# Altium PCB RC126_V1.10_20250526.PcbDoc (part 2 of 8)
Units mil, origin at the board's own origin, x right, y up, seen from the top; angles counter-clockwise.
Board outline 6299.62 x 3544.12 mil, 4 copper layers (Top, GND, Power, Bottom), stack 35.4 mil thick; 509 components, 417 nets, 1867 pads, 2150 vias.
Unrouted connection lines stored in the file: 1451.
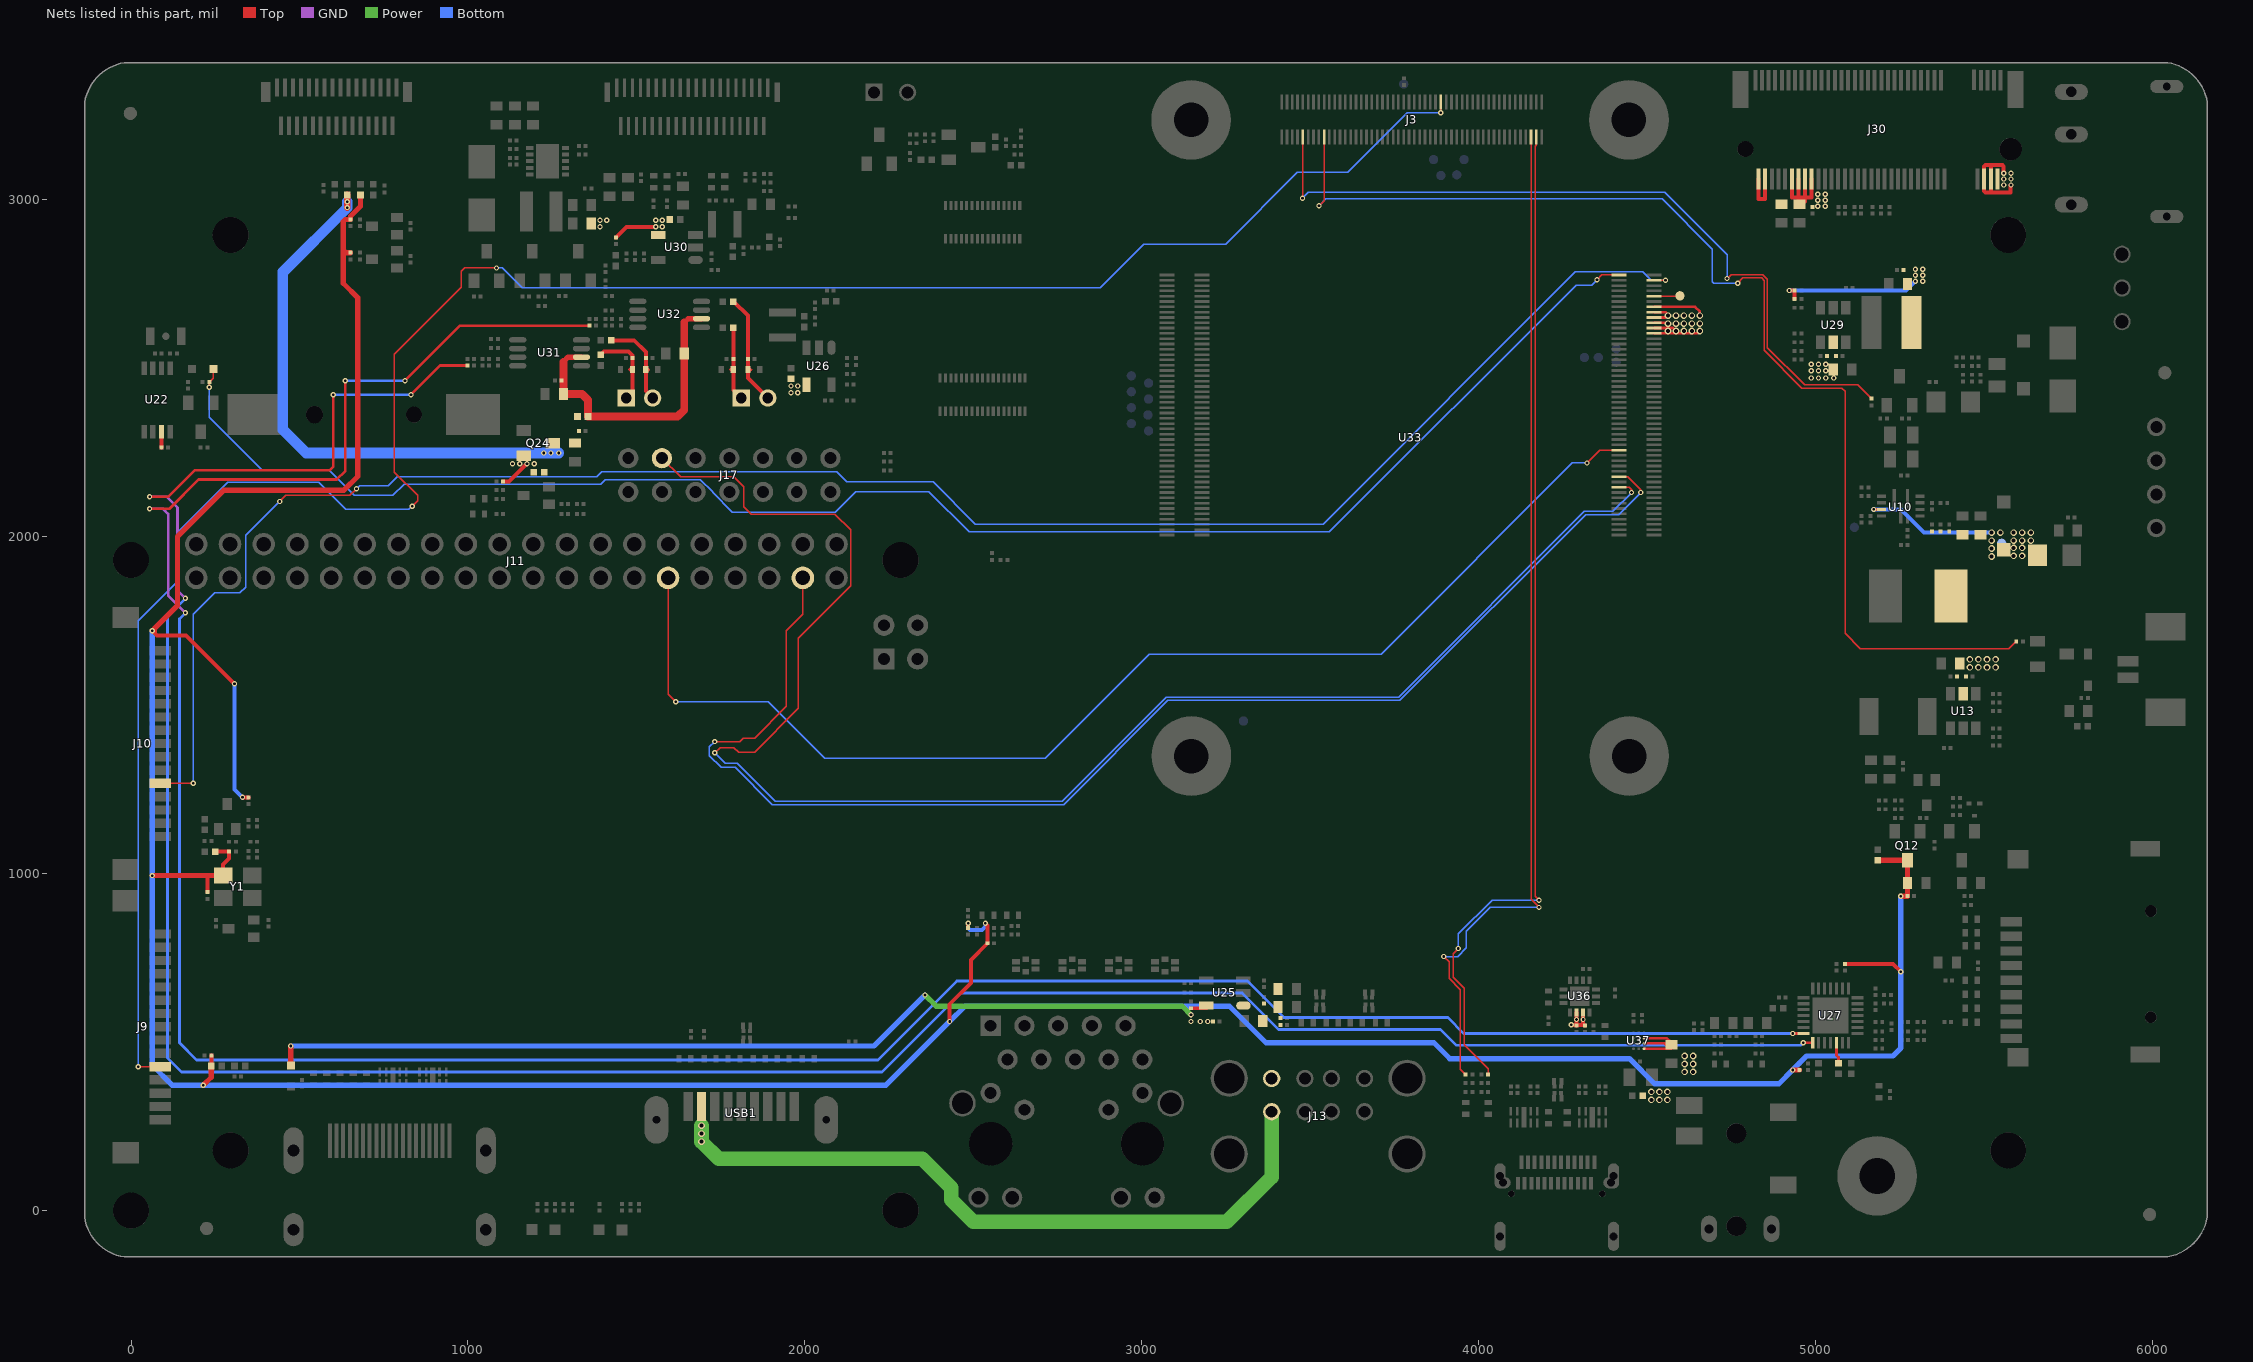
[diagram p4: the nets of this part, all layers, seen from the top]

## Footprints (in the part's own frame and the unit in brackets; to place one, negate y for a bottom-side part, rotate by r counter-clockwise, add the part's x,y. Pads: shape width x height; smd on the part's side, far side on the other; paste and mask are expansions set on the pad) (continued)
ESD_D0402 [mm]
  rect 0.4x0.55 smd: 1(-0.45,0) 2(0.45,0)
  Top region: 0.318,0.178 0.152,0.013 0.324,-0.159 0.324,0.165 0.318,0.165 0.318,0.178
  Top region: 0.368,0.279 0.095,0.006 0.375,-0.273 0.375,0.267 0.368,0.267 0.368,0.279
  Top region: -0.305,-0.165 -0.14,0 -0.311,0.171 -0.311,-0.152 -0.305,-0.152 -0.305,-0.165
  Top region: -0.356,-0.267 -0.083,0.006 -0.362,0.286 -0.362,-0.254 -0.356,-0.254 -0.356,-0.267
  Top lines w0.051: -0.495,-0.178 -0.305,-0.178 ; -0.495,0.191 -0.305,0.191 ; -0.457,-0.14 -0.267,-0.14 ; -0.457,0.152 -0.267,0.152 ; -0.432,0.114 -0.241,0.114 ; -0.419,-0.102 -0.229,-0.102 ; -0.406,0.089 -0.216,0.089 ; -0.394,-0.064 -0.203,-0.064 ; -0.381,0.064 -0.191,0.064 ; -0.356,-0.038 -0.165,-0.038 ; -0.343,0.038 -0.152,0.038 ; -0.33,-0.013 -0.14,-0.013 ; -0.318,0.013 -0.127,0.013 ; 0.14,0 0.33,0 ; 0.152,0.025 0.343,0.025 ; 0.165,-0.025 0.356,-0.025 ; 0.178,0.051 0.368,0.051 ; 0.203,-0.051 0.394,-0.051 ; 0.216,0.076 0.406,0.076 ; 0.229,-0.076 0.419,-0.076 ; 0.241,0.114 0.432,0.114 ; 0.254,-0.102 0.445,-0.102 ; 0.279,-0.14 0.47,-0.14 ; 0.279,0.152 0.47,0.152 ; 0.318,-0.178 0.508,-0.178 ; 0.318,0.191 0.508,0.191
  silkscreen extent -0.82,-0.41 0.85,0.42
FB0201 [mm]
  rect 0.3x0.3 smd: 1(-0.25,0) 2(0.25,0)
  silkscreen extent -0.5,-0.25 0.5,0.25
FB0402 [mm]
  rect 0.5x0.5 smd: 1(-0.4,0) 2(0.4,0)
  silkscreen extent -0.8,-0.4 0.8,0.4
FB0603 [mm]
  rect 0.7x0.9 smd: 1(-0.7,0) 2(0.7,0)
  silkscreen extent -1.2,-0.6 1.2,0.6
FB1206 [mm]
  rect 1.4x1.6 smd mask+0.05: 1(-1.3,0) 2(1.3,0)
  silkscreen extent -2.2,-1 2.2,1
FPC_15_1D0_LIE [mil]
  rect 27.6x63 smd: 1(-551.17,0) 2(-511.77,0) 3(-472.47,0) 4(-433.07,0) 5(-393.7,0) 6(-354.33,0) 7(-314.96,0) 8(-275.59,0) 9(-236.22,0) 10(-196.85,0) 11(-157.48,0) 12(-118.11,0) 13(-78.74,0) 14(-39.37,0) 15(0,0)
  rect 63x78.7 smd: 16(98.43,102.4) 17(-649.57,102.4)
  silkscreen extent -661,-77 114,193
FPC_31P_0D3_LIE [mm]
  rect 0.3x1.372 smd: 1(0,0) 2(0.3,2.875) 3(0.6,0) 4(0.9,2.875) 5(1.2,0) 6(1.5,2.875) 7(1.8,0) 8(2.1,2.875) 9(2.4,0) 10(2.7,2.875) 11(3,0) 12(3.3,2.875) 13(3.6,0) 14(3.9,2.875) 15(4.2,0) 16(4.5,2.875) 17(4.8,0) 18(5.1,2.875) 19(5.4,0) 20(5.7,2.875) 21(6,0) 22(6.3,2.875) 23(6.6,0) 24(6.9,2.875) 25(7.2,0) 26(7.5,2.875) 27(7.8,0) 28(8.1,2.875) 29(8.4,0) 30(8.7,2.875) 31(9,0)
  rect 0.7x1.5 smd: 32(9.84,0.335) 33(-0.84,0.335)
  silkscreen extent -1.07,-1.53 10,3.31
FPC_39P_0D3_LIE [mil]
  rect 54x10 smd: 1(0,0) 2(-113.18,11.81) 3(0,23.62) 4(-113.18,35.43) 5(0,47.24) 6(-113.18,59.06) 7(0,70.87) 8(-113.18,82.68) 9(0,94.49) 10(-113.18,106.3) 11(0,118.11) 12(-113.18,129.92) 13(0,141.73) 14(-113.18,153.54) 15(0,165.35) 16(-113.18,177.17) 17(0,188.98) 18(-113.18,200.79) 19(0,212.6) 20(-113.18,224.41) 21(0,236.22) 22(-113.18,248.03) 23(0,259.84) 24(-113.18,271.65) 25(0,283.46) 26(-113.18,295.28) 27(0,307.09) 28(-113.18,318.9) 29(0,330.71) 30(-113.18,342.52) 31(0,354.33) 32(-113.18,366.14) 33(0,377.95) 34(-113.18,389.76) 35(0,401.57) 36(-113.18,413.39) 37(0,425.2) 38(-113.18,437.01) 39(0,448.82)
  rect 59.06x15.75 smd: 40(-13.18,476.38) 41(-13.18,-27.56)
  silkscreen extent -130,-33 71,483
HOLE_2D7_6D0_A [mm]
  round 6 / inner round 3.2 / far side round 6 hole 2.7: 1(0,0)
HOLE_R6_2D7MM [mm]
  round 2.7 hole 2.7 unplated: 1(0,0)
  Top keep-out region: 3.003,0 2.774,1.149 2.123,2.123 1.149,2.774 0,3.003 0,3.003 -1.149,2.774 -2.123,2.123 -2.774,1.149 -3.003,0 -3.003,0 -2.774,-1.149 -2.123,-2.123 -1.149,-2.774 0,-3.003 0,-3.003 1.149,-2.774 2.123,-2.123 2.774,-1.149 3.003,0
  Bottom keep-out region: 3.003,0 2.774,1.149 2.123,2.123 1.149,2.774 0,3.003 0,3.003 -1.149,2.774 -2.123,2.123 -2.774,1.149 -3.003,0 -3.003,0 -2.774,-1.149 -2.123,-2.123 -1.149,-2.774 0,-3.003 0,-3.003 1.149,-2.774 2.123,-2.123 2.774,-1.149 3.003,0
L_2520 [mm]
  rect 0.6x2 smd: 1(0.947,0.006) 2(-0.953,0.006)
  Top keep-out region: -0.66,1 0.63,1 0.63,-1 -0.66,-1 -0.66,1
  silkscreen extent -1.33,-1.07 1.33,1.08
L_3015 [mil]
  rect 39x118 smd mask+3: 1(-44.85,0) 2(43.43,0)
  silkscreen extent -20,-59 20,59
L_4020 [mm]
  rect 1.5x4 smd mask+0.05: 1(-1.5,0) 2(1.5,0)
  silkscreen extent -2.1,-2.1 2.1,2.1
L_5020 [mm]
  rect 1.4x2.8 smd: 1(-2.2,0) 2(2.2,0)
  silkscreen extent -2.7,-2.55 2.7,2.55
L_6050 [mm]
  rect 2.5x4 smd: 1(-2.56,-0.07) 2(2.39,-0.07)
  silkscreen extent -3.79,-3.35 3.6,3.28
LED_D0603 [mm]
  rect 0.8x0.8 smd: 1(-0.869,0.001) 2(0.869,-0.001)
  silkscreen extent -1.41,-0.65 1.41,0.65
M2-M_KEY_SM_75_0D5 [mm]
  rect 0.3x1.55 smd mask+0.05: 1(-9.25,3.725) 2(-9,-3.725) 3(-8.75,3.725) 4(-8.5,-3.725) 5(-8.25,3.725) 6(-8,-3.725) 7(-7.75,3.725) 8(-7.5,-3.725) 9(-7.25,3.725) 10(-7,-3.725) 11(-6.75,3.725) 12(-6.5,-3.725) 13(-6.25,3.725) 14(-6,-3.725) 15(-5.75,3.725) 16(-5.5,-3.725) 17(-5.25,3.725) 18(-5,-3.725) 19(-4.75,3.725) 20(-4.5,-3.725) 21(-4.25,3.725) 22(-4,-3.725) 23(-3.75,3.725) 24(-3.5,-3.725) 25(-3.25,3.725) 26(-3,-3.725) 27(-2.75,3.725) 28(-2.5,-3.725) 29(-2.25,3.725) 30(-2,-3.725) 31(-1.75,3.725) 32(-1.5,-3.725) 33(-1.25,3.725) 34(-1,-3.725) 35(-0.75,3.725) 36(-0.5,-3.725) 37(-0.25,3.725) 38(0,-3.725) 39(0.25,3.725) 40(0.5,-3.725) 41(0.75,3.725) 42(1,-3.725) 43(1.25,3.725) 44(1.5,-3.725) 45(1.75,3.725) 46(2,-3.725) 47(2.25,3.725) 48(2.5,-3.725) 49(2.75,3.725) 50(3,-3.725) 51(3.25,3.725) 52(3.5,-3.725) 53(3.75,3.725) 54(4,-3.725) 55(4.25,3.725) 56(4.5,-3.725) 57(4.75,3.725) 58(5,-3.725) 67(7.25,3.75) 68(7.5,-3.725) 69(7.75,3.725) 70(8,-3.725) 71(8.25,3.725) 72(8.5,-3.725) 73(8.75,3.725) 74(9,-3.725) 75(9.25,3.725)
  round 1.2 hole 1.2 unplated: 76(-10,-1.475)
  round 1.7 hole 1.7 unplated: 77(10,-1.475)
  rect 1.2x2.8 smd mask+0.05: G1(-10.35,3.025) G2(10.35,3.025)
  silkscreen extent -9.54,-2.7 8.8,4.95
MARK [mm]
  round 1 smd: 1(0,0)
  silkscreen extent -1.65,-1.65 1.65,1.65
MLP14_0D5_2D5 [mm]
  rect 0.6x0.3 smd: 1(-1.21,0.5) 2(-1.21,0) 3(-1.21,-0.5) 8(1.21,-0.5) 9(1.21,0) 10(1.21,0.5)
  rect 0.3x0.6 smd: 4(-0.75,-1.21) 5(-0.25,-1.21) 6(0.25,-1.21) 7(0.75,-1.21) 11(0.75,1.21) 12(0.25,1.21) 13(-0.25,1.21) 14(-0.75,1.21)
  rect 1.45x1.45 smd: 15(0,0)
  silkscreen extent -2.48,-1.25 1.25,1.25
MSOP8_0D65_3 [mil]
  rect 40x16 smd mask+2.5: 1(0,0) 2(0,-25.59) 3(0,-51.18) 4(0,-76.77) 5(188.98,-76.77) 6(188.98,-51.18) 7(188.98,-25.59) 8(188.98,0)
  silkscreen extent -20,-90 209,40
MSOP8_0D65_5D0 [mm]
  oval 1.3x0.41 smd mask+0.05: 1(-2.4,0.975) 2(-2.4,0.325) 3(-2.4,-0.325) 4(-2.4,-0.975) 5(2.4,-0.975) 6(2.4,-0.325) 7(2.4,0.325) 8(2.4,0.975)
  silkscreen extent -2.71,-1.63 1.6,1.92
OSC_SM2_3D2X1D5 [mm]
  rect 0.65x1.3 smd: 1(0,0) 2(2.35,0)
  round 0.55 smd: 3(1.175,0)
  silkscreen extent -0.6,-0.8 2.9,0.8
OSC_SM4_3D2X2D5 [mm]
  rect 1.4x1.2 smd: 1(-1.1,-0.85) 2(1.1,-0.85) 3(1.1,0.85) 4(-1.1,0.85)
  silkscreen extent -1.6,-2.02 1.6,1.26
QFN12_0D5_2 [mm]
  rect 1.5x0.25 smd: 1(-0.55,0.5) 2(-0.55,-0.5) 7(0.55,0)
  rect 0.25x0.7 smd: 3(-0.75,-1.45) 4(-0.25,-1.45) 5(0.25,-1.45) 6(0.75,-1.45) 9(0.75,1.45) 10(0.25,1.45) 11(-0.25,1.45) 12(-0.75,1.45)
  rect 0.7x0.25 smd: 8(0.95,0.5)
  silkscreen extent -1.81,-1.5 1,1.5
QFN28_0D45_4 [mm]
  rect 0.9x0.25 smd mask+0.05: 1(-2.05,1.35) 2(-2.05,0.9) 3(-2.05,0.45) 4(-2.05,0) 5(-2.05,-0.45) 6(-2.05,-0.9) 7(-2.05,-1.35) 15(2.05,-1.35) 16(2.05,-0.9) 17(2.05,-0.45) 18(2.05,0) 19(2.05,0.45) 20(2.05,0.9) 21(2.05,1.35)
  rect 0.25x0.9 smd mask+0.05: 8(-1.35,-2.05) 9(-0.9,-2.05) 10(-0.45,-2.05) 11(0,-2.05) 12(0.45,-2.05) 13(0.9,-2.05) 14(1.35,-2.05) 22(1.35,2.05) 23(0.9,2.05) 24(0.45,2.05) 25(0,2.05) 26(-0.45,2.05) 27(-0.9,2.05) 28(-1.35,2.05)
  rect 2.7x2.7 smd mask+0.05: 29(0,0)
  Top keep-out region: -1.524,1.524 -1.524,-1.524 1.524,-1.524 1.524,1.524 -1.524,1.524
  silkscreen extent -2.97,-2 2,2.03
R0201 [mm]
  rect 0.3x0.3 smd: 1(-0.25,0) 2(0.25,0)
  silkscreen extent -0.5,-0.25 0.5,0.25
R0402 [mm]
  rect 0.5x0.5 smd: 1(-0.4,0) 2(0.4,0)
  silkscreen extent -0.8,-0.4 0.8,0.4
R0603 [mm]
  rect 0.7x0.9 smd: 1(-0.7,0) 2(0.7,0)
  silkscreen extent -1.2,-0.6 1.2,0.6
RJ45_LED_TH22_LIE [mm]
  rect 1.524x1.524 hole 0.9 mask+0.05: 1(0,0)
  round 1.524 / inner round 1.1 / far side round 1.524 hole 0.9 mask+0.05: 2(1.27,-2.54) 3(2.54,0) 4(3.81,-2.54) 5(5.08,0) 6(6.35,-2.54) 7(7.62,0) 8(8.89,-2.54) 9(10.16,0) 10(11.43,-2.54) 11(0,-5.06) 12(2.54,-6.33) 13(8.89,-6.33) 14(11.43,-5.06) 18(12.36,-12.95)
  round 1.524 hole 1.02 mask+0.05: 15(-0.92,-12.95) 16(1.62,-12.95) 17(9.82,-12.95)
  round 2 / inner round 2.2 / far side round 2.2 hole 1.6 mask+0.15: 19(-2.13,-5.84) 20(13.57,-5.84)
  round 3.25 hole 3.25: 21(0.005,-8.89) 22(11.435,-8.89)
  silkscreen extent -2.34,-19.63 13.77,1.72
SD_SM9_1D1_15D75 [mm]
  rect 1.6x0.7 smd: 1(-10.516,3.2) 2(-10.516,2.1) 3(-10.516,1) 4(-10.516,-0.1) 5(-10.516,-1.2) 6(-10.516,-2.3) 7(-10.516,-3.4) 8(-10.516,-4.5) 9(-10.516,-5.6)
  rect 1.6x1.4 smd: 10(-10.016,-7) 13(-10.016,7.9)
  rect 2.2x1.2 smd: 11(-0.416,-6.8) 12(-0.416,8.7)
  round 0.9 hole 0.9 unplated: 14(0,4) 15(0,-4)
  silkscreen extent -10.52,-6.4 3.98,8.3
SOD_123 [mm]
  rect 1x1 smd: 1(-1.8,0) 2(1.8,0)
  silkscreen extent -1.11,-0.9 1.13,0.9
SOD_323 [mm]
  rect 0.8x0.6 smd mask+0.05: 1(-1.2,0) 2(1.2,0)
  silkscreen extent -0.67,-0.65 0.64,0.65
SOD_523 [mm]
  rect 0.6x0.6 smd mask+0.05: 1(0,0.8) 2(0,-0.8)
  silkscreen extent -0.4,-0.6 0.4,0.6
SON10_0D5_1 [mm]
  rect 0.2x0.675 smd: 1(-1,-0.437) 2(-0.5,-0.437) 4(0.5,-0.437) 5(1,-0.437) 6(1,0.437) 7(0.5,0.437) 9(-0.5,0.437) 10(-1,0.437)
  rect 0.4x0.775 smd: 3(0,-0.388) 8(0,0.388)
  silkscreen extent -1.46,-1.39 1.25,0.5
SOT23_5 [mm]
  oval 0.6x1.1 smd: 1(-0.95,-1.4)
  rect 0.6x1.1 smd: 2(0,-1.4) 3(0.95,-1.4) 4(0.95,1.4) 5(-0.95,1.4)
  silkscreen extent -2,-1.45 1.5,0.55
SOT23_6 [mm]
  rect 0.7x1 smd mask+0.05: 1(-0.95,-1.3) 2(0,-1.3) 3(0.95,-1.3) 4(0.95,1.3) 5(0,1.3) 6(-0.95,1.3)
  silkscreen extent -1.75,-2.42 1.75,0.7
SOT_23 [mm]
  rect 0.8x1.1 smd: 1(-0.95,-1.1) 2(0.95,-1.1) 3(0,1.1)
  silkscreen extent -1.6,-0.9 1.6,0.9
SOT_323 [mm]
  rect 0.7x0.9 smd: 1(-0.65,-0.95) 2(0.65,-0.95) 3(0,0.95)
  silkscreen extent -1.1,-0.67 1.1,0.67
SOT_723 [mm]
  rect 0.4x0.3 smd: 1(0,0) 2(0.805,0) 3(0.403,0.94)
  silkscreen extent -0.22,-0.17 1.02,1.12
TP_0R70 [mm]
  round 0.7 smd: 1(0,0)
  silkscreen extent -0.45,-0.45 0.45,0.45
TYPEC_SM24P_0D5 [mm]
  rect 0.3x1 smd: A1(1.61,5.59) A2(2.11,5.59) A3(2.61,5.59) A4(3.11,5.59) A5(3.61,5.59) A6(4.11,5.59) A7(4.61,5.59) A8(5.11,5.59) A9(5.61,5.59) A10(6.11,5.59) A11(6.61,5.59) A12(7.11,5.59)
  rect 0.3x0.95 smd: B1(6.86,3.99) B2(6.36,3.99) B3(5.86,3.99) B4(5.36,3.99) B5(4.86,3.99) B6(4.36,3.99) B7(3.86,3.99) B8(3.36,3.99) B9(2.86,3.99) B10(2.36,3.99) B11(1.86,3.99) B12(1.36,3.99)
  oval 0.85x1.9 / inner oval 0.85x1.8 / far side oval 1x2.1 hole 0.6 slot 1.5 at 90 deg: E1(0,4.55) E6(8.56,4.55)
  oval 1.2x0.85 / inner oval 1.2x0.85 / far side oval 1.2x0.9 hole 0.6 slot 1 at 0 deg: E2(0.21,4.04) E5(8.38,4.04)
  oval 0.85x2.2 / inner oval 0.85x2.2 / far side oval 1x2.2 hole 0.6 slot 1.9 at 90 deg: E3(0,0)
  oval 0.85x2.2 / inner oval 0.85x2.2 / far side oval 1x2.25 hole 0.6 slot 1.9 at 90 deg: E4(8.56,0)
  round 0.5 hole 0.5: H1(0.85,3.2) H2(7.71,3.2)
  silkscreen extent -0.24,-2.35 8.87,5.55
USB_SM9_2D0_LIE [mm]
  rect 0.7x2.2 smd: 1(-3,0) 2(-1,0) 3(1,0) 4(3,0) 5(4,0) 6(2,0) 7(0,0) 8(-2,0) 9(-4,0)
  oval 1.8x3.6 / inner oval 0.7x2.6 / far side oval 1.8x3.6 hole 0.584 slot 2.489 at 90 deg: 10(-6.4,-1) 11(6.4,-1)
  silkscreen extent -9.28,-14.64 9.29,0.92
WLCSP12_0D4_1D5 [mm]
  round 0.215 smd mask+0.05: A1(0,0) A2(0.4,0) A3(0.8,0) B1(0,-0.4) B2(0.4,-0.4) B3(0.8,-0.4) C1(0,-0.8) C2(0.4,-0.8) C3(0.8,-0.8) D1(0,-1.2) D2(0.4,-1.2) D3(0.8,-1.2)
  silkscreen extent -0.66,-1.53 1.12,0.61

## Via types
v1: diameter 15.75, hole 7.87, Top to Bottom, 2047 vias
v2: diameter 19.68, hole 11.81, Top to Bottom, 103 vias

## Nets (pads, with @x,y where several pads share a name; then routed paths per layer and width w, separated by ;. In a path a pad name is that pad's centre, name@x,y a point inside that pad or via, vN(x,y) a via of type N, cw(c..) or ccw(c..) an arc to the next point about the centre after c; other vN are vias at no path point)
3V3_PCIE: C217.1 C218.1 C219.1 C223.1 C224.1 C225.1 J30.2 J30.4 J30.12 J30.14 J30.16 J30.18 J30.70 J30.72 J30.74 L21.2 R285.1 | length 1224.6
  Top w11.81: J30.2@4829.92,3061.22 4829.92,3001.97 4849.61,3001.97 J30.4@4849.61,3061.22 ; v1(4921.26,2730.32) R285.1@4937.01,2730.32 C217.1@4937.01,2704.72 ; J30.12@4928.35,3061.22 4928.35,3005.91 4987.4,3005.91 J30.18@4987.4,3061.22 ; J30.14@4948.03,3061.22 4948.03,2994.09 4967.72,2994.09 J30.16@4967.72,3061.22 ; v1(5557.09,3078.74) 5557.09,3098.43 5553.15,3102.36 5518.9,3102.36 ; v1(5578.74,3043.31) 5576.77,3041.34 5576.77,3021.65 5518.9,3021.65 ; 5518.9,3021.65 5503.15,3021.65 5499.21,3025.59 J30.70@5499.21,3061.22 5499.21,3098.43 5503.15,3102.36 5518.9,3102.36 ; 5518.9,3021.65 J30.72@5518.9,3061.22 5518.9,3102.36
  Bottom w11.81: v1(4921.26,2730.32) 5267.72,2730.32 v1(5295.28,2757.87)
  other v1: 5316.93,2757.87 5295.28,2775.59 5316.93,2775.59 5295.28,2793.31 5316.93,2793.31 5005.91,2980.32 5027.56,2980.32 5005.91,2998.03 5027.56,2998.03 5005.91,3015.75 5027.56,3015.75 5557.09,3043.31 5557.09,3061.02 5578.74,3061.02 5578.74,3078.74
3V3_S0: C157.1 C158.1 C194.1 FB1.2 FB3.2 FB4.2 FB14.1 FB15.1 Q12.3 R8.2 R11.2 R164.1 R211.2 R238.1 R248.2 R264.2 R270.2 Y1.4 | length 11029.8
  Top w3.94: 226.38,994.09 228.35,994.09
  Top w11.81: v1(62.99,1720.47) 70.87,1712.6 ; 70.87,1728.35 70.87,1712.6 ; R264.2@226.38,944.88 226.38,994.09 ; FB1.2@238.19,429.13 R211.2@238.19,460.63 ; FB3.2@250,1064.96 C194.1@291.34,1064.96 291.34,1045.27 273.62,1027.56 Y1.4@273.62,994.09 ; v1(307.09,1562.99) 163.39,1706.69 76.77,1706.69 70.87,1712.6 ; v1(330.71,1226.38) R270.2@348.43,1226.38 ; v1(2429.13,561.02) 2429.13,612.2 2492.13,675.2 2492.13,744.09 R238.1@2541.34,793.31 2541.34,846.46 v1(2535.43,852.36) ; R248.2@2484.25,838.58 v1(2484.25,852.36) ; FB14.1@5086.61,732.28 5228.35,732.28 v1(5251.97,708.66)
  Top w15.75: v1(62.99,994.09) 226.38,994.09 ; v1(62.99,1720.47) 70.87,1728.35 137.8,1795.28 137.8,2000 275.59,2137.8 631.89,2137.8 673.23,2179.13 673.23,2708.66 629.92,2751.97 629.92,2850.39 ; v1(214.57,372.05) 238.19,395.67 FB1.2@238.19,429.13 ; 228.35,994.09 Y1.4@273.62,994.09 ; R8.2@651.57,2842.52 637.8,2842.52 629.92,2850.39 ; FB4.2@681.1,3013.78 681.1,2980.32 651.57,2950.79 R11.2@651.57,2940.94 635.83,2940.94 629.92,2935.04 629.92,2850.39 ; v1(4931.1,417.32) FB15.1@4950.79,417.32 ; R164.1@5183.07,1039.37 Q12.3@5271.65,1039.37 C157.1@5271.65,972.44 C158.1@5271.65,933.07 v1(5251.97,933.07)
  Bottom w11.81: v1(307.09,1562.99) 307.09,1250 v1(330.71,1226.38) ; v1(2484.25,852.36) 2484.25,838.58 2490.16,832.68 2525.59,832.68 2535.43,842.52 v1(2535.43,852.36)
  Bottom w15.75: v1(62.99,1720.47) v1(62.99,994.09) 62.99,431.1 122.05,372.05 v1(214.57,372.05) 2240.16,372.05 v1(2429.13,561.02) 2474.41,606.3 3259.84,606.3 3368.11,498.03 3866.14,498.03 3913.39,450.79 4446.85,450.79 4521.65,375.98 4889.76,375.98 v1(4931.1,417.32) 4972.44,458.66 5228.35,458.66 5251.97,482.28 v1(5251.97,708.66) v1(5251.97,933.07)
5V_S0: C297.1 C298.1 FB5.2 FB22.1 Q24.3 R342.1 | length 1641.1
  Top w19.68: v1(641.73,2976.38) FB5.2@641.73,3013.78
  Bottom w31.5: v1(641.73,2994.09) v1(641.73,2976.38) 450.79,2785.43 450.79,2316.93 519.69,2248.03 v1(1269.68,2248.03)
  other v1: 1224.41,2248.03 1246.06,2248.03
5V_SPK_AMP: C282.1 C285.1 C292.1 FB22.2 U31.6 U32.6 | length 898.1
  Top w3.94: C282.1@1277.56,2462.6 1283.46,2462.6
  Top w15.75: 1283.46,2518.7 1297.24,2532.48 U31.6@1336.61,2532.48 ; 1641.73,2634.84 1653.54,2646.65 U32.6@1692.91,2646.65
  Top w23.62: 1283.46,2518.7 1283.46,2462.6 C285.1@1283.46,2423.23 1338.58,2423.23 1356.3,2405.51 FB22.2@1356.3,2356.3 1622.05,2356.3 1641.73,2375.98 C292.1@1641.73,2543.31 1641.73,2634.84
5V_USB_HOST: C198.1 C199.1 C213.1 C214.1 C215.1 C216.1 J13.1 J13.5 U25.1 USB1.1 | length 2164.3
  Top w3.94: USB1.1@1692.91,271.65 USB1.1@1692.91,328.35
  Power w43.31: v2(1692.91,251.97) v2(1692.91,228.35) v2(1692.91,204.72) 1744.09,153.54 2348.43,153.54 2434.06,67.91 2434.06,32.48 2500,-33.46 3251.97,-33.46 3385.04,99.61 J13.1@3385.04,293.31
32KOUT_RTC: R263.2 U22.7 | length 47.2
  Top w11.81: R263.2@90.55,2263.78 U22.7@90.55,2311.02
+5V_INPUT: C90.1 C106.1 C107.1 C144.1 C146.1 C153.1 C154.1 C196.1 C202.1 C211.1 C212.1 C241.1 C255.1 C270.1 C271.1 D1.2 D8.1 FB2.1 L2.2 Q24.2 R18.1 R185.1 R255.1 R277.1 R278.2 R342.2 R344.2 R352.1 TP7.1 U10.5 U13.5 U25.5 U26.4 U29.5 U30.4 U33.77 U33.79 U33.81 U33.83 U33.85 U33.87 U36.12 U36.13 U37.A1 U37.B1 U37.C1 | length 4384
  Top w7.87: U37.A1@4490.16,480.32 C255.1@4570.87,480.32 ; U37.B1@4490.16,496.06 4551.18,496.06 4564.96,482.28 4564.96,480.32 C255.1@4570.87,480.32 ; U37.C1@4490.16,511.81 4557.09,511.81 4570.87,498.03 C255.1@4570.87,492.13 C255.1@4570.87,480.32 ; U33.77@4520.08,2603.15 4648.43,2603.15 v2(4655.51,2610.24) ; U33.79@4520.08,2618.9 4575.98,2618.9 v2(4584.65,2610.24) ; U33.81@4520.08,2634.65 4558.27,2634.65 v2(4561.02,2631.89) ; U33.83@4520.08,2650.39 4553.15,2650.39 4558.27,2655.51 v2(4561.02,2655.51) 4561.02,2658.27 4553.15,2666.14 U33.85@4520.08,2666.14 ; U33.87@4520.08,2681.89 4641.73,2681.89 4655.51,2668.11 v2(4655.51,2655.51)
  Top w9.84: v1(5171.26,2080.71) U10.5@5194.88,2080.71
  Top w11.81: R344.2@1104.33,2163.39 1122.05,2163.39 v1(1175.2,2216.54) ; R255.1@1438.98,2887.8 1470.47,2919.29 v1(1557.09,2919.29) ; R277.1@3145.67,600.39 U25.5@3190.95,600.39 ; v1(4273.62,551.18) C270.1@4312.99,551.18 ; C271.1@4289.37,549.21 U36.12@4289.37,588.19 ; U36.13@4309.06,588.19 v1(4309.06,566.93) 4309.06,555.12 ; 4309.06,555.12 C270.1@4314.96,549.21 C270.1@4312.99,551.18 ; 4309.06,555.12 4313.98,550.2 C270.1@4312.99,551.18
  Top w15.75: D8.1@474.41,431.1 v1(474.41,488.19)
  Power w15.75: v1(2356.3,639.76) 2389.76,606.3 3120.08,606.3 v1(3145.67,580.71)
  Bottom w11.81: v1(5171.26,2080.71) 5251.97,2080.71 5320.87,2011.81 v2(5521.65,2011.81)
  Bottom w15.75: v1(474.41,488.19) 2204.72,488.19 v1(2356.3,639.76)
  other v1: 3145.67,561.02 3173.23,561.02 3194.88,561.02 4289.37,566.93 1131.89,2216.54 1153.54,2216.54 1196.85,2216.54 1958.66,2427.17 1978.35,2427.17 1958.66,2446.85 1978.35,2446.85 4986.22,2470.47 5007.87,2470.47 5029.53,2470.47 5053.15,2470.47 4986.22,2492.13 5007.87,2492.13 5029.53,2492.13 4986.22,2511.81 5007.87,2511.81 5029.53,2511.81 1391.73,2919.29 1576.77,2919.29 1391.73,2938.98 1411.42,2938.98 1557.09,2938.98 1576.77,2938.98
  other v2: 4511.81,328.74 4535.43,328.74 4559.06,328.74 4511.81,352.36 4535.43,352.36 4559.06,352.36 4610.24,411.42 4635.83,411.42 4610.24,435.04 4635.83,435.04 4610.24,458.66 4635.83,458.66 5456.69,1612.2 5482.28,1612.2 5507.87,1612.2 5533.46,1612.2 5456.69,1635.83 5482.28,1635.83 5507.87,1635.83 5533.46,1635.83 5521.65,1940.94 5586.61,1942.91 5612.2,1942.91 5521.65,1964.57 5586.61,1966.54 5612.2,1966.54 5521.65,1988.19 5586.61,1988.19 5612.2,1988.19 5637.8,1988.19 5547.24,2011.81 5586.61,2011.81 5612.2,2011.81 5637.8,2011.81 4561.02,2610.24 4608.27,2610.24 4631.89,2610.24 4584.65,2631.89 4608.27,2631.89 4631.89,2631.89 4655.51,2631.89 4584.65,2655.51 4608.27,2655.51 4631.89,2655.51
ADCVREF_ES8388: C273.1 U27.19 | length 63.5
  Top w7.87: U27.19@5061.03,498.03 5061.03,460.63 5066.93,454.72 C273.1@5066.93,437.01
AUD_LINEOUT_L: C289.1 U27.15 | length 8054
  Top w7.87: v1(55.12,2118.11) 110.24,2118.11 188.98,2196.85 588.58,2196.85 600.39,2208.66 v1(600.39,2421.26) ; v1(830.71,2421.26) 917.32,2507.87 C289.1@998.03,2507.87 ; v1(4962.6,498.03) U27.15@4990.16,498.03
  GND w7.87: v1(55.12,2118.11) 106.3,2118.11 137.8,2086.61 137.8,1840.55 v1(161.42,1816.93)
  Bottom w7.87: v1(161.42,1816.93) 108.27,1763.78 108.27,452.76 149.61,411.42 2228.35,411.42 2462.6,645.67 3297.24,645.67 3405.51,537.4 3885.83,537.4 3933.07,490.16 4954.72,490.16 v1(4962.6,498.03) ; v1(600.39,2421.26) v1(830.71,2421.26)
AUD_LINEOUT_R: C296.1 U27.14 | length 8347.6
  Top w7.87: v1(55.12,2082.68) 114.17,2082.68 200.79,2169.29 610.24,2169.29 635.83,2194.88 v1(635.83,2462.6) ; v1(812.99,2462.6) 976.38,2625.98 C296.1@1360.24,2625.98 ; v1(4931.1,525.59) U27.14@4962.6,525.59
  GND w7.87: v1(55.12,2082.68) 94.49,2082.68 110.24,2066.93 110.24,1824.8 v1(161.42,1773.62)
  Bottom w7.87: v1(161.42,1773.62) 143.7,1755.91 143.7,498.03 194.88,446.85 2216.54,446.85 2450.79,681.1 3312.99,681.1 3421.26,572.83 3907.63,572.83 3954.87,525.59 v1(4931.1,525.59) ; v1(635.83,2462.6) v1(812.99,2462.6)
AUD_SPK1N: C288.1 D34.2 FB23.2 J18.2 | length 261.3
  Top w11.81: FB23.2@1425.2,2582.68 1492.13,2582.68 1527.56,2547.24 C288.1@1527.56,2529.53 D34.2@1527.56,2496.06 1527.56,2431.89 J18.2@1548.03,2411.42
AUD_SPK1P: C287.1 D33.2 FB24.2 J18.1 | length 237.3
  Top w11.81: FB24.2@1393.7,2539.37 1403.54,2549.21 1476.38,2549.21 1488.19,2537.4 C287.1@1488.19,2529.53 D33.2@1488.19,2496.06 1488.19,2430.32 J18.1@1469.29,2411.42
AUD_SPK2N: C295.1 D52.2 FB25.2 J19.2 | length 329
  Top w11.81: FB25.2@1787.4,2696.85 1789.37,2696.85 1830.71,2655.51 C295.1@1830.71,2527.56 D52.2@1830.71,2496.06 1830.71,2470.47 J19.2@1889.76,2411.42
AUD_SPK2P: C294.1 D45.2 FB26.2 J19.1 | length 218.4
  Top w11.81: FB26.2@1787.4,2620.08 C294.1@1787.4,2527.56 D45.2@1787.4,2496.06 1787.4,2435.04 J19.1@1811.02,2411.42
BT_NDIS: P28.1 U33.91 | length 76.9
  Top w3.94: U33.91@4520.08,2713.39 4595.28,2713.39 P28.1@4596.46,2714.57
CAM1_GPIO: J10.5 U33.97 | length 5652.2
  Top w3.94: J10.5@86.61,1267.72 v1(185.04,1267.72) ; v1(440.94,2104.33) 458.66,2122.05 649.61,2122.05 v1(669.29,2141.73) ; U33.97@4520.08,2760.63 v1(4553.54,2760.63)
  Bottom w3.94: v1(185.04,1267.72) 185.04,1769.69 248.03,1832.68 322.89,1832.68 340.55,1850.33 340.55,2003.94 v1(440.94,2104.33) ; v1(669.29,2141.73) 679.13,2151.57 763.78,2151.57 789.37,2177.17 1381.89,2177.17 1397.64,2192.91 2094.49,2192.91 2124.02,2163.39 2379.92,2163.39 2505.91,2037.4 3537.4,2037.4 4285.43,2785.43 4486.22,2785.43 4511.02,2760.63 v1(4553.54,2760.63)
CAM_GPIO: J3.39 J9.5 | length 6490.5
  Top w3.94: v1(21.65,427.17) J9.5@86.61,427.17 ; v1(834.65,2090.55) 850.39,2106.3 850.39,2122.05 781.5,2190.94 781.5,2541.34 980.31,2740.16 980.31,2787.4 990.16,2797.24 v1(1084.65,2797.24) ; v1(3887.01,3258.27) 3887.01,3275.1 J3.39@3887.01,3289.77
  Bottom w3.94: v1(21.65,427.17) 21.65,1750 141.73,1870.08 141.73,2015.75 287.4,2161.42 557.09,2161.42 637.8,2080.71 824.8,2080.71 v1(834.65,2090.55) ; v1(1084.65,2797.24) 1102.36,2797.24 1161.42,2738.19 2875.98,2738.19 3005.91,2868.11 3248.03,2868.11 3460.63,3080.71 3610.24,3080.71 3787.8,3258.27 v1(3887.01,3258.27)
CAN1_RX_M3: J11.37 U33.24 | length 4002.9
  Top w3.94: v1(1732.28,1391.73) 1807.09,1391.73 1816.93,1401.57 1850.39,1401.57 1944.88,1496.06 1944.88,1720.87 1993.7,1769.69 J11.37@1993.7,1877.56 ; U33.24@4415.35,2177.95 4442.13,2177.95 4480.32,2139.76 v1(4480.32,2130.71)
  Bottom w3.94: v1(1732.28,1391.73) 1716.54,1375.98 1716.54,1350.39 1751.97,1314.96 1793.31,1314.96 1903.54,1204.72 2767.72,1204.72 3076.77,1513.78 3765.75,1513.78 4316.93,2064.96 4414.57,2064.96 v1(4480.32,2130.71)
CAN1_TX_M3: J11.29 U33.34 | length 3624.2
  Top w3.94: J11.29@1593.7,1877.56 1593.7,1532.28 v1(1616.14,1509.84) ; v1(4320.87,2218.5) 4359.06,2256.69 U33.34@4415.35,2256.69
  Bottom w3.94: v1(1616.14,1509.84) 1891.73,1509.84 2059.06,1342.52 2712.6,1342.52 3021.65,1651.57 3710.63,1651.57 4277.56,2218.5 v1(4320.87,2218.5)
CM4_PWR_TEST: J3.92 R2.1 | length 2302.4
  Top w3.94: v1(3476.38,3003.94) 3477.56,3005.12 3477.56,3179.5 J3.92@3477.56,3185.83 ; v1(4736.22,2765.75) 4748.03,2777.56 4842.52,2777.56 4856.3,2763.78 4856.3,2561.02 4966.54,2450.79 5124.02,2450.79 R2.1@5165.35,2409.45
  Bottom w3.94: v1(3476.38,3003.94) 3494.09,3021.65 4551.18,3021.65 4736.22,2836.61 v1(4736.22,2765.75)
DP_TX_AUXN_SBU2: C250.1 J3.6 | length 3045.2
  Top w3.94: v1(3895.67,753.94) 3911.42,738.19 3911.42,688.98 3944.88,655.51 3944.88,419.29 C250.1@3960.63,403.54 ; J3.6@4154.72,3168.6 4154.72,923.23 v1(4178.35,899.61) ; J3.6@4154.73,3168.6 J3.6@4154.73,3185.83
  Bottom w3.94: v1(3895.67,753.94) 3937.01,753.94 3962.6,779.53 3962.6,828.74 4033.46,899.61 v1(4178.35,899.61)
DP_TX_AUXP_SBU1: C249.1 J3.4 | length 3018.5
  Top w3.94: v1(3938.98,777.56) 3923.23,761.81 3923.23,692.91 3956.69,659.45 3956.69,492.13 4027.56,421.26 C249.1@4027.56,403.54 ; J3.4@4170.47,3171.4 4170.47,3161.42 4167.32,3158.27 4167.32,932.28 v1(4178.35,921.26) ; J3.4@4170.48,3171.4 J3.4@4170.48,3185.83
  Bottom w3.94: v1(3938.98,777.56) 3938.98,820.87 4039.37,921.26 v1(4178.35,921.26)
EEPROM_NWP: J17.4 U33.20 | length 4799.8
  Top w3.94: J17.4@1575.59,2232.68 1631.1,2177.17 1789.37,2177.17 1818.9,2147.64 1818.9,2088.58 1840.55,2066.93 2088.58,2066.93 2135.83,2019.69 2135.83,1854.33 1980.32,1698.82 1980.32,1490.16 1850.39,1360.24 1803.15,1360.24 1789.37,1374.02 1748.03,1374.02 v1(1732.28,1358.27) ; U33.20@4415.35,2146.46 4446.06,2146.46 4452.76,2139.76 v1(4452.76,2130.71)
  Bottom w3.94: v1(1732.28,1358.27) 1763.78,1326.77 1799.21,1326.77 1911.42,1214.57 2763.78,1214.57 3072.83,1523.62 3761.81,1523.62 4312.99,2074.8 4396.85,2074.8 v1(4452.76,2130.71)
EXT_RST: D30.1 R265.1 U33.100 | length 4879.1
  Top w3.94: v1(232.28,2442.91) R265.1@232.28,2458.66 244.09,2470.47 D30.1@244.09,2498.03 ; v1(4350.39,2761.81) 4364.96,2776.38 U33.100@4415.35,2776.38
  Bottom w3.94: v1(232.28,2442.91) 232.28,2354.53 387.99,2198.82 586.07,2198.82 662.84,2122.05 777.09,2122.05 810.56,2155.51 1393.94,2155.51 1407.72,2169.29 1689.75,2169.29 1726.38,2132.67 1726.38,2131.11 1784.65,2072.83 2090.09,2072.83 2151.11,2133.86 2367.13,2133.86 2487.2,2013.78 3555.95,2013.78 4288.23,2746.06 4334.65,2746.06 v1(4350.39,2761.81)
FAN-PWM: J3.84 R14.1 | length 3460.1
  Top w3.94: v1(3525.59,2982.28) 3540.55,2997.24 3540.55,3181.5 J3.84@3540.56,3185.83 ; v1(4767.72,2751.97) 4783.46,2767.72 4838.58,2767.72 4846.46,2759.84 4846.46,2553.15 4958.66,2440.94 5076.77,2440.94 5086.61,2431.1 5086.61,1712.6 5131.89,1667.32 5572.83,1667.32 R14.1@5594.49,1688.98
  Bottom w3.94: v1(3525.59,2982.28) 3545.28,3001.97 4543.31,3001.97 4692.91,2852.36 4692.91,2755.91 4696.85,2751.97 v1(4767.72,2751.97)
